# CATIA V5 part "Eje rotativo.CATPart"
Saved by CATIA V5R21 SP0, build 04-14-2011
Part number: Part1
Material "Steel": density 7860 kg/m3, Young's modulus 2e+11 Pa, Poisson ratio 0.266, thermal expansion 1.17e-05 1/K
Bounding box of the stored display mesh (mm): x -18.951 to 18.951, y -275 to 275, z -18.952 to 18.952
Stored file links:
  C:\Users\David\Desktop\TFG\catia\Eje rotativo.CATPart
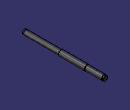
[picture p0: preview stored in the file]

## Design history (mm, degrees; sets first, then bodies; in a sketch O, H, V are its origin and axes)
Body1 (main body), material "Steel"
  Sketch1 on yz-plane, origin (0, 0, 0), H (0, 1, 0), V (0, 0, 1)
    point P1 (-275, 0)
    line L1 (-275, 0) -> (-275, 15)
    line L2 (-275, 15) -> (-265, 15)
    line L3 (-265, 15) -> (-265, 16)
    line L4 (-265, 16) -> (-25, 16)
    line L5 (-25, 16) -> (-25, 19)
    line L6 (-25, 19) -> (150, 19)
    line L7 (150, 19) -> (150, 17.5)
    point P8 (150, 17.5)
    line L8 (150, 17.5) -> (265, 17.5)
    line L9 (265, 17.5) -> (265, 15)
    point P10 (265, 15)
    line L10 (265, 15) -> (275, 15)
    line L11 (275, 15) -> (275, 0)
    point P12 (275, 0)
    axis line L12 (328.9605, 0) -> (-353.7328, 0)
    point P13 (328.9605, 0)
    length L1 = 15
    length L2 = 10
    length L10 = 10
    distance L11 P8 = 125
    distance L1 V = 275
    length L6 = 175
    distance L11 V = 275
    distance H L6 = 19
    distance H L8 = 17.5
    distance H L4 = 16
    coincidence: P1 H, P10 L2, P12 H, P13 H
    vertical: L1 V, L3 V, L5 V, L7 V, L9 V, L11 V
    horizontal: L2 H, L4 H, L6 H, L8 H, L10 H, L12 H
  Shaft1: profile Sketch1, axis Sketch1.L12, angle 360
  Fillet1: radius 3, on edge [face of Shaft1 from Sketch1.L10 | face of Shaft1 from Sketch1.L9]; edge [face of Shaft1 from Sketch1.L8 | face of Shaft1 from Sketch1.L7]; edge [face of Shaft1 from Sketch1.L5 | face of Shaft1 from Sketch1.L4]; edge [face of Shaft1 from Sketch1.L3 | face of Shaft1 from Sketch1.L2]
  Point1: (0, 50, 19)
